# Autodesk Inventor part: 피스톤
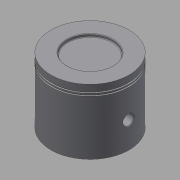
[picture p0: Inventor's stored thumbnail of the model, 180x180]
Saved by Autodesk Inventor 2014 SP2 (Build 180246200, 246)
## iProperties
Created: 2016-11
Part Number: 피스톤
Material: 강철, 탄소
Document SubType Name: Modeling
Designer: mduedu
Density: 7.87 g/cm^3
Mass: 410.154 g
Surface Area: 237.492 cm^2
Volume: 52.1161 cm^3
Appearance: 기본값
Author: mduedu
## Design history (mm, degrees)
sketch "스케치1"
  geometry: C1 r 30 at (0, 0); 1 further point
  constraints: 1 centre point, 1 coincident
  dimensions: "d0" = 60 diameter of C1
extrude "돌출1" new body sketch "스케치1" distance "d1" = 50; taper "d2" = 0 deg
sketch "스케치2"
  geometry: C1 r 28 at (0, 0); 1 further point
  constraints: 1 centre point, 1 coincident
  dimensions: "d3" = 56 diameter of C1
extrude "돌출2" cut sketch "스케치2" distance "d4" = 45; taper "d5" = 0 deg
sketch "스케치3"
  geometry: L1 (30, 0)-(30, 50) reference; L2 (30, 45)-(29, 45); L3 (29, 45)-(29, 44); L4 (29, 44)-(30, 44); L5 (30, 44)-(30, 45); L6 (30, 43)-(29, 43); L7 (29, 43)-(29, 42); L8 (29, 42)-(30, 42); L9 (30, 42)-(30, 43); L10 (30, 50)-(-30, 50) reference; L11 (0, 50)-(0, 0)
  constraints: 18 end point, 4 parallel, 3 equal length, 3 perpendicular, 2 horizontal, 2 point on line, 1 midpoint
  dimensions: "d6" = 1 distance of L2.start L2.end; "d8" = 5 distance between parallel lines of L10 L2; "d9" = 1 distance between parallel lines of L6 L4
revolve "회전1" sketch "스케치3" stored, may be unused: angle "d10" = 90 deg
node "작업 평면1"
sketch "스케치4"
  geometry: L1 (0, -22.978)-(45, -22.978) reference; L2 (45, -22.978)-(45, 22.978) reference; L3 (45, 22.978)-(0, 22.978) reference; L4 (0, 22.978)-(0, 25.377) reference; L5 (0, 25.377)-(42, 25.377) reference; L6 (42, 25.377)-(42, 24.187) reference; L7 (42, 24.187)-(43, 24.187) reference; L8 (43, 24.187)-(43, 25.377) reference; L9 (43, 25.377)-(44, 25.377) reference; L10 (44, 25.377)-(44, 24.187) reference; L11 (44, 24.187)-(45, 24.187) reference; L12 (45, 24.187)-(45, 25.377) reference; L13 (45, 25.377)-(50, 25.377) reference; L14 (50, 25.377)-(50, -25.377) reference; L15 (50, -25.377)-(45, -25.377) reference; L16 (45, -25.377)-(45, -24.187) reference; L17 (45, -24.187)-(44, -24.187) reference; L18 (44, -24.187)-(44, -25.377) reference; L19 (44, -25.377)-(43, -25.377) reference; L20 (43, -25.377)-(43, -24.187) reference; L21 (43, -24.187)-(42, -24.187) reference; L22 (42, -24.187)-(42, -25.377) reference; L23 (42, -25.377)-(0, -25.377) reference; L24 (0, -25.377)-(0, -22.978) reference; L25 (12.5, 22.978)-(45, 22.978); L26 (45, 22.978)-(45, -22.978); L27 (45, -22.978)-(12.5, -22.978); L28 (12.5, -22.978)-(12.5, 22.978); C1 r 7.5 at (20, 0); C2 r 4 at (20, 0); 1 further point
  constraints: 8 end point, 2 centre point, 2 parallel, 1 coincident, 1 horizontal, 1 horizontal alignment, 1 perpendicular, 1 point on line, 1 tangent
  dimensions: "d12" = 15 diameter of C1; "d13" = 8 diameter of C2; "d14" = 20 distance of point (0, 0) C1.centre
  node "절단 모서리 투영1"
extrude "돌출3" join sketch "스케치4" stored distance "d15" = 11.75; taper "d16" = 0 deg
extrude "돌출4" cut sketch "스케치4" stored distance "d17" = 72; taper "d18" = 0 deg
fillet "모깎기2" dims "d20" = 3
chamfer "모따기1" distance "d21" = 0.5; stored, may be unused: second distance "d22" = 2, angle "d23" = 45 deg
chamfer "모따기2" distance "d24" = 0.5; stored, may be unused: second distance "d25" = 2, angle "d26" = 45 deg
sketch "스케치5"
  geometry: C1 r 17.5 at (0, 0); 1 further point
  constraints: 1 centre point, 1 coincident
  dimensions: "d27" = 35 diameter of C1
extrude "돌출5" cut sketch "스케치5" distance "d28" = 2; taper "d29" = 0 deg
fillet "모깎기3" dims "d30" = 0.5
node "솔리드1"
mirror "대칭1"
other parameters: "d11" = -16
